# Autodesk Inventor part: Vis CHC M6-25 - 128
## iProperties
Created: 2011-12
Part Number: Vis CHC M6-25 - 128
Document SubType Name: Modeling
Designer: A
Manufacturer: Standard
Standards Organization: Custom
Author: A
Norme de conversion: STEP AP203
Nom du fichier: vischcm6-25.STEP
Préprocesseur: SolidWorks 2006104
Postprocesseur: Build: 096e, Release: 9 RTM - Date: Thu 06/17/2004
Unités envoyées: MILLIMETERS
Incertitude: 1e-05
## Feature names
1. Base1
